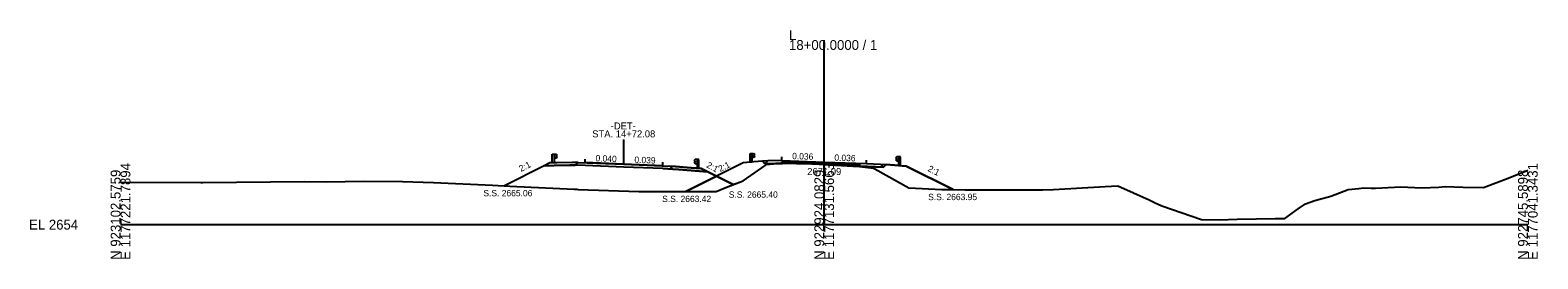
# Model space of a CAD drawing. Extents: x -26 to 1403, y -10 to 9563.
# Drawn here: x -25.7 to 402.8, y 7990.3 to 8055.2 of the extents above; entities that cross this region are included whole.
import ezdxf

# ---------------------------------------------------------------- set-up
doc = ezdxf.new("R2010")
doc.units = 0
for name, color, linetype in [('Exist Cross Section Cell', 7, 'Continuous'), ('Exist XS Center Line Elevation Label', 7, 'Continuous'), ('Exist XS Ground Line', 7, 'Continuous'), ('Prop XS Ditch Slope Text', 7, 'Continuous'), ('Prop XS Dump Level', 7, 'Continuous'), ('Prop XS Earthwork Shape', 7, 'Continuous'), ('Prop XS EOT Tick Mark', 7, 'Continuous'), ('Prop XS Finish Grade', 7, 'Continuous'), ('Prop XS Finish Grade Earthwork', 7, 'Continuous'), ('Prop XS Finish Grade Paved Shoulder', 7, 'Continuous'), ('Prop XS Finish Grade Pavement', 7, 'Continuous'), ('Prop XS Guardrail', 7, 'Continuous'), ('Prop XS Pvmt Edge Slope', 7, 'Continuous'), ('Prop XS SE Text', 7, 'Continuous'), ('Prop XS Shoulder Borrow Shape', 7, 'Continuous'), ('Prop XS Side Slope Text', 7, 'Continuous'), ('Prop XS SS Elevation Text', 7, 'Continuous'), ('Prop XS Subgrade Earthwork', 7, 'Continuous'), ('Prop XS Vertical Lines', 7, 'Continuous'), ('Prop XS Wedging', 7, 'Continuous')]:
    doc.layers.add(name, color=color, linetype=linetype)

msp = doc.modelspace()

# ---------------------------------------------------------------- linework, layer by layer
at = {"layer": 'Exist Cross Section Cell'}
for p, q in [((200, 8000), (200, 8052.4)), ((0, 8000), (200, 8000)), ((200, 8000), (400, 8000))]:
    msp.add_line(p, q, dxfattribs=at)
at = {"layer": 'Exist XS Ground Line'}
for p, q in [((176.93, 8012.42), (183.24, 8016.79)), ((183.24, 8016.79), (183.75, 8017.13)), ((183.75, 8017.13), (184.56, 8017.2)), ((184.56, 8017.2), (187.68, 8017.47)), ((187.68, 8017.47), (196.51, 8017.24)), ((196.51, 8017.24), (198.54, 8017.18)), ((198.54, 8017.18), (200, 8017.09)), ((200, 8017.09), (208.18, 8016.6)), ((208.18, 8016.6), (210.07, 8016.48)), ((210.07, 8016.48), (210.81, 8016.41)), ((210.81, 8016.41), (213.98, 8016.06)), ((213.98, 8016.06), (214.38, 8015.84)), ((214.38, 8015.84), (224.01, 8010.42)), ((394.41, 8013.19), (400, 8015.44)), ((0, 8012.06), (22.84, 8012.01)), ((22.84, 8012.01), (23.41, 8012.01)), ((23.41, 8012.01), (52.21, 8012.21)), ((52.21, 8012.21), (58.65, 8012.2)), ((58.65, 8012.2), (69.1, 8012.3)), ((69.1, 8012.3), (80.18, 8012.29)), ((80.18, 8012.29), (88.97, 8011.93)), ((88.97, 8011.93), (105.75, 8011.25)), ((105.75, 8011.25), (110.62, 8010.97)), ((110.62, 8010.97), (128.93, 8010.07)), ((128.93, 8010.07), (129.66, 8010.04)), ((129.66, 8010.04), (130.08, 8010.01)), ((130.08, 8010.01), (147.29, 8009.39)), ((147.29, 8009.39), (161.81, 8009.42)), ((161.81, 8009.42), (169.34, 8009.39)), ((169.34, 8009.39), (171.55, 8010.39)), ((171.55, 8010.39), (176.93, 8012.42)), ((224.01, 8010.42), (233.48, 8010)), ((233.48, 8010), (240.06, 8009.9)), ((240.06, 8009.9), (254.35, 8009.92)), ((254.35, 8009.92), (262.09, 8009.92)), ((262.09, 8009.92), (265.15, 8010.02)), ((265.15, 8010.02), (279.83, 8010.87)), ((279.83, 8010.87), (283.45, 8011.02)), ((283.45, 8011.02), (292.4, 8007.02)), ((343.98, 8008.12), (348.89, 8010.02)), ((348.89, 8010.02), (351.99, 8010.24)), ((351.99, 8010.24), (353.33, 8010.49)), ((353.33, 8010.49), (355.44, 8010.37)), ((355.44, 8010.37), (356.68, 8010.38)), ((356.68, 8010.38), (363.85, 8010.73)), ((363.85, 8010.73), (369.9, 8010.5)), ((369.9, 8010.5), (374.67, 8010.66)), ((374.67, 8010.66), (376.51, 8010.87)), ((376.51, 8010.87), (381.6, 8010.64)), ((381.6, 8010.64), (387.37, 8010.56)), ((387.37, 8010.56), (394.41, 8013.19)), ((292.4, 8007.02), (294.03, 8006.15)), ((294.03, 8006.15), (295.93, 8005.37)), ((295.93, 8005.37), (307.26, 8001.42)), ((334.71, 8004.47), (336.8, 8005.92)), ((336.8, 8005.92), (339.46, 8006.84)), ((339.46, 8006.84), (343.98, 8008.12)), ((307.26, 8001.42), (312.37, 8001.39)), ((312.37, 8001.39), (317.42, 8001.55)), ((317.42, 8001.55), (328.16, 8001.72)), ((328.16, 8001.72), (330.95, 8001.76)), ((330.95, 8001.76), (334.71, 8004.47))]:
    msp.add_line(p, q, dxfattribs=at)
at = {"layer": 'Prop XS Dump Level'}
for p, q in [((188, 8018.21), (200, 8017.78)), ((130.04, 8017.68), (143.09, 8017.17)), ((143.09, 8017.17), (132.04, 8017.6)), ((154.15, 8016.73), (143.09, 8017.17)), ((143.09, 8017.17), (156.15, 8016.65)), ((200, 8017.78), (212, 8017.34))]:
    msp.add_line(p, q, dxfattribs=at)
at = {"layer": 'Prop XS Earthwork Shape'}
for p, q in [((182.43, 8018), (180, 8017.81)), ((183.15, 8017.28), (182.43, 8018)), ((120.4, 8016.7), (109.12, 8011.06)), ((123.24, 8016.76), (120.4, 8016.7)), ((127.66, 8016.85), (123.24, 8016.76)), ((129.24, 8016.88), (127.66, 8016.85)), ((132.04, 8016.77), (129.24, 8016.88)), ((143.09, 8016.33), (132.04, 8016.77)), ((154.15, 8015.9), (143.09, 8016.33)), ((157.01, 8015.78), (154.15, 8015.9)), ((158.62, 8015.65), (157.01, 8015.78)), ((166.94, 8014.99), (158.62, 8015.65)), ((160.7, 8009.42), (169.39, 8013.76)), ((169.39, 8013.76), (160.7, 8009.42)), ((169.39, 8013.76), (160.7, 8009.42)), ((169.39, 8013.76), (166.94, 8014.99)), ((177, 8017.57), (169.39, 8013.76)), ((174.16, 8011.38), (169.39, 8013.76)), ((174.16, 8011.38), (169.39, 8013.76)), ((169.39, 8013.76), (174.16, 8011.38)), ((176.93, 8012.42), (183.24, 8016.79)), ((186.18, 8017.34), (183.15, 8017.28)), ((183.24, 8016.79), (183.75, 8017.13)), ((183.75, 8017.13), (184.56, 8017.2)), ((184.56, 8017.2), (186.18, 8017.34)), ((187.68, 8017.47), (186.18, 8017.34)), ((186.18, 8017.34), (188.12, 8017.38)), ((188.12, 8017.45), (187.68, 8017.47)), ((188.12, 8017.38), (188.12, 8017.45)), ((188.12, 8017.45), (188.12, 8017.45)), ((216.86, 8016.33), (210.07, 8016.58)), ((210.07, 8016.58), (210.07, 8016.48)), ((210.07, 8016.48), (210.81, 8016.41)), ((210.81, 8016.41), (213.98, 8016.06)), ((213.98, 8016.06), (214.38, 8015.84)), ((214.38, 8015.84), (224.01, 8010.42)), ((217.6, 8017.07), (216.86, 8016.33)), ((220, 8016.88), (217.6, 8017.07)), ((221.14, 8016.78), (220, 8016.88)), ((236.63, 8009.95), (223.32, 8016.61)), ((109.12, 8011.06), (110.62, 8010.97)), ((110.62, 8010.97), (128.93, 8010.07)), ((128.93, 8010.07), (129.66, 8010.04)), ((129.66, 8010.04), (130.08, 8010.01)), ((130.08, 8010.01), (147.29, 8009.39)), ((147.29, 8009.39), (160.7, 8009.42)), ((160.7, 8009.42), (161.81, 8009.42)), ((160.7, 8009.42), (161.81, 8009.42)), ((161.81, 8009.42), (169.34, 8009.39)), ((161.81, 8009.42), (169.34, 8009.39)), ((169.34, 8009.39), (171.55, 8010.39)), ((169.34, 8009.39), (171.55, 8010.39)), ((171.55, 8010.39), (174.16, 8011.38)), ((171.55, 8010.39), (174.16, 8011.38)), ((174.16, 8011.38), (176.93, 8012.42)), ((224.01, 8010.42), (233.48, 8010)), ((233.48, 8010), (236.63, 8009.95))]:
    msp.add_line(p, q, dxfattribs=at)
for points in [[(180, 8017.81), (179.42, 8017.76), (178.92, 8017.72), (177, 8017.57)], [(223.32, 8016.61), (221.64, 8016.74), (221.14, 8016.78)]]:
    msp.add_lwpolyline(points, dxfattribs=at)
at = {"layer": 'Prop XS EOT Tick Mark'}
for p, q in [((132.04, 8017.6), (132.04, 8018.6)), ((188, 8018.21), (188, 8019.21)), ((212, 8017.34), (212, 8018.34)), ((154.15, 8016.73), (154.15, 8017.73))]:
    msp.add_line(p, q, dxfattribs=at)
at = {"layer": 'Prop XS Finish Grade'}
for p, q in [((184, 8018.13), (182.43, 8018)), ((130.04, 8017.68), (128.47, 8017.65)), ((156.15, 8016.65), (157.75, 8016.52)), ((216, 8017.2), (217.6, 8017.07))]:
    msp.add_line(p, q, dxfattribs=at)
at = {"layer": 'Prop XS Finish Grade Earthwork'}
for p, q in [((182.43, 8018), (180, 8017.81)), ((120.4, 8016.7), (109.12, 8011.06)), ((122.04, 8017.52), (120.4, 8016.7)), ((124.04, 8017.56), (122.04, 8017.52)), ((128.47, 8017.65), (124.04, 8017.56)), ((157.75, 8016.52), (162.15, 8016.17)), ((177, 8017.57), (160.7, 8009.42)), ((162.15, 8016.17), (165.04, 8015.94)), ((165.04, 8015.94), (166.94, 8014.99)), ((166.94, 8014.99), (174.16, 8011.38)), ((180, 8017.81), (177, 8017.57)), ((217.6, 8017.07), (220, 8016.88)), ((220, 8016.88), (223.32, 8016.61)), ((223.32, 8016.61), (236.63, 8009.95))]:
    msp.add_line(p, q, dxfattribs=at)
at = {"layer": 'Prop XS Finish Grade Paved Shoulder'}
for p, q in [((188, 8018.21), (184, 8018.13)), ((212, 8017.34), (216, 8017.2))]:
    msp.add_line(p, q, dxfattribs=at)
at = {"layer": 'Prop XS Finish Grade Pavement'}
for p, q in [((188, 8018.21), (200, 8017.78)), ((130.04, 8017.68), (143.09, 8017.17)), ((143.09, 8017.17), (156.15, 8016.65)), ((200, 8017.78), (212, 8017.34))]:
    msp.add_line(p, q, dxfattribs=at)
at = {"layer": 'Prop XS Guardrail'}
for p, q in [((122.71, 8020.03), (123.21, 8020.03)), ((122.71, 8017.53), (122.71, 8020.03)), ((123.21, 8020.03), (123.71, 8020.03)), ((123.21, 8020.03), (123.21, 8017.53)), ((123.71, 8018.9), (123.21, 8018.9)), ((123.71, 8020.03), (124, 8019.83)), ((124, 8019.71), (123.71, 8019.51)), ((123.71, 8019.51), (123.71, 8019.42)), ((123.71, 8019.42), (124, 8019.22)), ((124, 8019.1), (123.71, 8018.9)), ((124, 8019.83), (124.03, 8019.77)), ((124.03, 8019.77), (124, 8019.71)), ((124, 8019.22), (124.03, 8019.16)), ((124.03, 8019.16), (124, 8019.1)), ((163.07, 8018.29), (163.04, 8018.23)), ((163.04, 8018.23), (163.07, 8018.17)), ((163.36, 8018.49), (163.07, 8018.29)), ((163.07, 8018.17), (163.36, 8017.97)), ((163.36, 8017.88), (163.07, 8017.68)), ((163.86, 8018.49), (163.36, 8018.49)), ((163.36, 8017.97), (163.36, 8017.88)), ((164.36, 8018.49), (163.86, 8018.49)), ((163.86, 8018.49), (163.86, 8015.99)), ((164.36, 8015.99), (164.36, 8018.49)), ((178.92, 8020.22), (179.42, 8020.22)), ((178.92, 8017.72), (178.92, 8020.22)), ((179.42, 8020.22), (179.92, 8020.22)), ((179.42, 8020.22), (179.42, 8017.72)), ((179.92, 8019.09), (179.42, 8019.09)), ((179.92, 8020.22), (180.21, 8020.02)), ((180.21, 8019.9), (179.92, 8019.7)), ((179.92, 8019.7), (179.92, 8019.61)), ((179.92, 8019.61), (180.21, 8019.41)), ((180.21, 8019.29), (179.92, 8019.09)), ((180.21, 8020.02), (180.24, 8019.96)), ((180.24, 8019.96), (180.21, 8019.9)), ((180.21, 8019.41), (180.24, 8019.35)), ((180.24, 8019.35), (180.21, 8019.29)), ((220.35, 8019.04), (220.32, 8018.98)), ((220.32, 8018.98), (220.35, 8018.92)), ((220.35, 8018.43), (220.32, 8018.37)), ((220.32, 8018.37), (220.35, 8018.31)), ((220.64, 8019.24), (220.35, 8019.04)), ((220.35, 8018.92), (220.64, 8018.72)), ((220.64, 8018.63), (220.35, 8018.43)), ((220.35, 8018.31), (220.64, 8018.11)), ((221.14, 8019.24), (220.64, 8019.24)), ((220.64, 8018.72), (220.64, 8018.63)), ((220.64, 8018.11), (221.14, 8018.11)), ((221.64, 8019.24), (221.14, 8019.24)), ((221.14, 8019.24), (221.14, 8016.74)), ((221.64, 8016.74), (221.64, 8019.24)), ((163.07, 8017.68), (163.04, 8017.62)), ((163.04, 8017.62), (163.07, 8017.56)), ((163.07, 8017.56), (163.36, 8017.36)), ((163.36, 8017.36), (163.86, 8017.36))]:
    msp.add_line(p, q, dxfattribs=at)
at = {"layer": 'Prop XS Pvmt Edge Slope'}
for p, q in [((184, 8018.13), (183.15, 8017.28)), ((130.04, 8017.68), (129.24, 8016.88)), ((156.15, 8016.65), (157.01, 8015.78)), ((216, 8017.2), (216.86, 8016.33))]:
    msp.add_line(p, q, dxfattribs=at)
at = {"layer": 'Prop XS Shoulder Borrow Shape'}
for p, q in [((122.04, 8017.52), (120.4, 8016.7)), ((120.4, 8016.7), (123.24, 8016.76)), ((123.24, 8016.76), (127.66, 8016.85)), ((128.47, 8017.65), (124.04, 8017.56)), ((127.66, 8016.85), (129.24, 8016.88)), ((130.04, 8017.68), (128.47, 8017.65)), ((129.24, 8016.88), (130.04, 8017.68)), ((157.75, 8016.52), (156.15, 8016.65)), ((156.15, 8016.65), (157.01, 8015.78)), ((157.01, 8015.78), (158.62, 8015.65)), ((162.15, 8016.17), (157.75, 8016.52)), ((158.62, 8015.65), (166.94, 8014.99)), ((165.04, 8015.94), (164.36, 8015.99)), ((164.36, 8015.99), (164.36, 8015.99)), ((166.94, 8014.99), (165.04, 8015.94))]:
    msp.add_line(p, q, dxfattribs=at)
for points in [[(124.04, 8017.56), (123.21, 8017.54), (122.71, 8017.53), (122.04, 8017.52)], [(164.36, 8015.99), (163.86, 8016.03), (162.15, 8016.17)], [(164.36, 8015.99), (164.36, 8015.99)]]:
    msp.add_lwpolyline(points, dxfattribs=at)
at = {"layer": 'Prop XS Subgrade Earthwork'}
for p, q in [((183.15, 8017.28), (182.43, 8018)), ((123.24, 8016.76), (120.4, 8016.7)), ((127.66, 8016.85), (123.24, 8016.76)), ((129.24, 8016.88), (127.66, 8016.85)), ((132.04, 8016.77), (129.24, 8016.88)), ((143.09, 8016.33), (132.04, 8016.77)), ((154.15, 8015.9), (143.09, 8016.33)), ((154.15, 8015.9), (157.01, 8015.78)), ((157.01, 8015.78), (158.62, 8015.65)), ((158.62, 8015.65), (166.94, 8014.99)), ((188.12, 8017.38), (183.15, 8017.28)), ((188.12, 8017.38), (188.12, 8017.45)), ((210.07, 8016.58), (210.07, 8016.48)), ((210.07, 8016.58), (216.86, 8016.33)), ((216.86, 8016.33), (217.6, 8017.07))]:
    msp.add_line(p, q, dxfattribs=at)
at = {"layer": 'Prop XS Vertical Lines'}
msp.add_line((143.09, 8017.17), (143.09, 8024.17), dxfattribs=at)
at = {"layer": 'Prop XS Wedging'}
for points in [[(188.12, 8017.45), (188.12, 8017.96), (196.51, 8017.66), (198.54, 8017.59), (200, 8017.53), (200.12, 8017.53), (208.18, 8017.23), (210.07, 8017.16), (210.07, 8016.48), (208.18, 8016.6), (200.12, 8017.09), (200, 8017.1), (198.54, 8017.18), (196.51, 8017.24)], [(188.12, 8017.45), (188.12, 8017.96), (196.51, 8017.66), (198.54, 8017.59), (200, 8017.53), (200.12, 8017.53), (208.18, 8017.23), (210.07, 8017.16), (210.07, 8016.48), (208.18, 8016.6), (200.12, 8017.09), (200, 8017.1), (198.54, 8017.18), (196.51, 8017.24)], [(188.12, 8017.45), (188.12, 8017.71), (189, 8017.68), (189.26, 8017.43)], [(202.41, 8016.95), (202.65, 8017.19), (208.18, 8016.98), (210.07, 8016.91), (210.07, 8016.48), (208.18, 8016.6)]]:
    msp.add_lwpolyline(points, close=True, dxfattribs=at)

# ---------------------------------------------------------------- texts
at = {"layer": 'Exist Cross Section Cell'}
for s, p in [('18+00.0000 / 1', (190, 8049.6)), ('L', (190, 8052.4)), ('EL 2654', (-26, 7998.6))]:
    msp.add_text(s, height=2.8, dxfattribs=at).set_placement(p)
for s, p in [('N 923102.5759', (0, 7990)), ('E 1177221.7894', (2.8, 7990)), ('N 922924.0829', (200, 7990)), ('E 1177131.5663', (202.8, 7990)), ('N 922745.5898', (400, 7990)), ('E 1177041.3431', (402.8, 7990))]:
    msp.add_text(s, height=2.8, rotation=90, dxfattribs=at).set_placement(p)
at = {"layer": 'Exist XS Center Line Elevation Label'}
msp.add_text('2671.09', height=2, dxfattribs=at).set_placement((195.18, 8014.09))
at = {"layer": 'Prop XS Ditch Slope Text'}
msp.add_text('2:1', height=1.8, rotation=331.9406, dxfattribs=at).set_placement((166.35, 8016.36))
at = {"layer": 'Prop XS Dump Level'}
for s, p in [('Case1', (124.04, 8017.4)), ('Case1', (162.15, 8016.05)), ('Case2', (180, 8017.77)), ('Case2', (220, 8016.84))]:
    msp.add_text(s, height=0.04, dxfattribs=at).set_placement(p)
at = {"layer": 'Prop XS SE Text'}
for s, rotation, p in [('0.040', 357.7377, (134.97, 8017.99)), ('0.039', 357.7385, (146.02, 8017.55)), ('0.036', 357.9265, (190.86, 8018.61)), ('0.036', 357.9265, (202.86, 8018.17))]:
    msp.add_text(s, height=1.8, rotation=rotation, dxfattribs=at).set_placement(p)
at = {"layer": 'Prop XS Side Slope Text'}
for rotation, p in [(26.5651, (113.81, 8014.96)), (26.5651, (170.46, 8014.92)), (333.4349, (229.27, 8015.31))]:
    msp.add_text('2:1', height=1.8, rotation=rotation, dxfattribs=at).set_placement(p)
at = {"layer": 'Prop XS SS Elevation Text'}
for s, p in [('S.S. 2665.06', (103.13, 8008.05)), ('S.S. 2665.40', (172.89, 8007.64)), ('S.S. 2663.42', (153.95, 8006.42)), ('S.S. 2663.95', (229.54, 8006.96))]:
    msp.add_text(s, height=1.8, dxfattribs=at).set_placement(p)
at = {"layer": 'Prop XS Vertical Lines'}
for s, p in [('STA. 14+72.08', (134.07, 8024.77)), ('-DET-', (139.33, 8027.02))]:
    msp.add_text(s, height=2, dxfattribs=at).set_placement(p)

doc.saveas('drawing.dxf')
